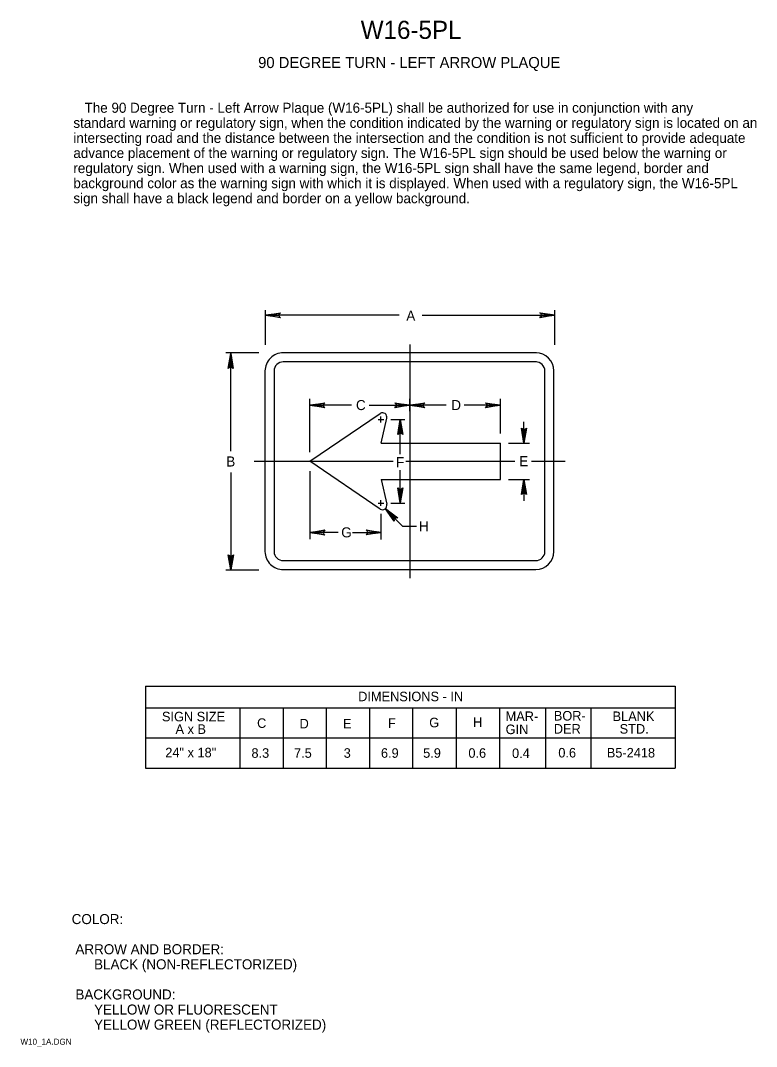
# Model space of a CAD drawing. Extents: x 0.013 to 0.196, y 0.004 to 0.259.
import ezdxf

# ---------------------------------------------------------------- set-up
doc = ezdxf.new("R2010")
doc.units = 0
for name, color, linetype in [('1', 7, 'Continuous'), ('2', 7, 'Continuous'), ('3', 7, 'Continuous')]:
    doc.layers.add(name, color=color, linetype=linetype)

# ---------------------------------------------------------------- blocks, each defined once
blk = doc.blocks.new('RARROW')
at = {"layer": '3'}
for p, q in [((-2.156, 0.28500000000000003), (-2.2665, 0.384625)), ((-2.2665, 0.384625), (0, 0)), ((0, 0), (-2.2665, -0.379125)), ((-2.156, 0.28500000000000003), (-2.075625, 0.12075)), ((0, 0), (-2.156, 0.28500000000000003)), ((-2.14975, -0.2705), (0, 0)), ((-2.075625, 0.12075), (0, 0)), ((0, 0), (-2.074, -0.108)), ((-2.2665, -0.379125), (-2.14975, -0.2705)), ((-2.074, -0.108), (-2.14975, -0.2705))]:
    blk.add_line(p, q, dxfattribs=at)

msp = doc.modelspace()

# ---------------------------------------------------------------- linework, layer by layer
at = {"layer": '1'}
for p, q in [((0.10950949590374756, 0.1784793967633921), (0.10950949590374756, 0.1204219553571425)), ((0.10234676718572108, 0.15397023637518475), (0.1320844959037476, 0.15397023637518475)), ((0.07079216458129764, 0.14947023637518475), (0.10538538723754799, 0.14947023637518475)), ((0.10848253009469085, 0.14947023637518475), (0.13531668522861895, 0.14947023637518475)), ((0.13531668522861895, 0.14947023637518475), (0.13561545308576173, 0.14947023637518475)), ((0.1398231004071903, 0.14947023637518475), (0.14818860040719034, 0.14947023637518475)), ((0.10234676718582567, 0.14497023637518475), (0.13208449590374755, 0.14497023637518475))]:
    msp.add_line(p, q, dxfattribs=at)
at = {"layer": '3'}
for p, q in [((0.07359843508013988, 0.17841642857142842), (0.07359843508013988, 0.18703855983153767)), ((0.1455984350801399, 0.17841642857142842), (0.1455984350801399, 0.18703855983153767)), ((0.10689328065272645, 0.18578855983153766), (0.07363359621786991, 0.18578855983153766)), ((0.1125947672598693, 0.18578855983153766), (0.1455984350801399, 0.18578855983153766)), ((0.07196701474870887, 0.17641355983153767), (0.0637585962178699, 0.17641355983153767)), ((0.0650085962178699, 0.1519761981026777), (0.0650085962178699, 0.17641355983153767)), ((0.14105197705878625, 0.17641642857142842), (0.07796701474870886, 0.17641642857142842)), ((0.14099731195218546, 0.17416642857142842), (0.07796701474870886, 0.17416642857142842)), ((0.07346701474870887, 0.17191642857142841), (0.07346701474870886, 0.12701630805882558)), ((0.07571701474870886, 0.17191642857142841), (0.07571701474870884, 0.1270163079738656)), ((0.14311543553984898, 0.12702017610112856), (0.14311543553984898, 0.171920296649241)), ((0.14536543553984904, 0.12702017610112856), (0.145365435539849, 0.171920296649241)), ((0.0846506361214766, 0.15176078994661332), (0.0846506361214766, 0.16495536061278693)), ((0.09499236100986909, 0.16340406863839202), (0.0846506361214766, 0.16340406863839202)), ((0.09939918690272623, 0.16340406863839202), (0.10950949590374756, 0.16340406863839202)), ((0.10950749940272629, 0.1619188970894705), (0.10950749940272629, 0.16495536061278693)), ((0.11854522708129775, 0.16340406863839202), (0.10950949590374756, 0.16340406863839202)), ((0.1320844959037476, 0.16340406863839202), (0.1230516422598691, 0.16340406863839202)), ((0.1320844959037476, 0.15633322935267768), (0.1320844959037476, 0.16495536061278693)), ((0.0846506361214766, 0.14947023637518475), (0.1021648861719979, 0.16137481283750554)), ((0.10161684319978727, 0.1598577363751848), (0.10233395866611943, 0.1598577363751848)), ((0.10233395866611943, 0.1598577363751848), (0.10233395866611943, 0.16057485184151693)), ((0.10233395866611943, 0.15914062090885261), (0.10233395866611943, 0.1598577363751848)), ((0.10233395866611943, 0.1598577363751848), (0.1030510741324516, 0.1598577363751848)), ((0.10234676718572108, 0.15397023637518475), (0.10377893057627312, 0.16017724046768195)), ((0.10481032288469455, 0.1598577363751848), (0.10825237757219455, 0.1598577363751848)), ((0.10712677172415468, 0.15126902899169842), (0.10712677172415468, 0.15904849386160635)), ((0.1379153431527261, 0.1539742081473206), (0.1379153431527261, 0.15928200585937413)), ((0.13208449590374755, 0.14497023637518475), (0.1320844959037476, 0.15397023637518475)), ((0.13410605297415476, 0.15397023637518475), (0.13925979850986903, 0.15397023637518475)), ((0.10216792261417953, 0.13755506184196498), (0.0846506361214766, 0.14947023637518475)), ((0.0650085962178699, 0.14667306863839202), (0.0650085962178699, 0.12258255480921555)), ((0.0846506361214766, 0.14704617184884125), (0.0846506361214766, 0.1301261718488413)), ((0.10712677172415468, 0.13909420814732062), (0.10712677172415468, 0.14722331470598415)), ((0.10234676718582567, 0.14497023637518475), (0.103778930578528, 0.13876323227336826)), ((0.13410605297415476, 0.14497023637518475), (0.13925979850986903, 0.14497023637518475)), ((0.1379153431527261, 0.14497023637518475), (0.1379153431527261, 0.13966243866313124)), ((0.10161684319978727, 0.13908273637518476), (0.10233395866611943, 0.13908273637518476)), ((0.10233395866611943, 0.13908273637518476), (0.10233395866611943, 0.13979985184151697)), ((0.10233395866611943, 0.13836562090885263), (0.10233395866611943, 0.13908273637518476)), ((0.10233395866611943, 0.13908273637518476), (0.1030510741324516, 0.13908273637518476)), ((0.10480954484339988, 0.13908273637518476), (0.10825159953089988, 0.13908273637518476)), ((0.10233395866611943, 0.1363890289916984), (0.10233395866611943, 0.12998902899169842)), ((0.1034524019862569, 0.13766902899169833), (0.10771129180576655, 0.13333585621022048)), ((0.10771129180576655, 0.13333585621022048), (0.11115334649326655, 0.13333585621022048)), ((0.09166954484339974, 0.13175474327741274), (0.0846506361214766, 0.13175474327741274)), ((0.09522383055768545, 0.13175474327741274), (0.10236383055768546, 0.13175474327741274)), ((0.07796701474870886, 0.12476630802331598), (0.14086543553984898, 0.12476630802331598)), ((0.07796701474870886, 0.12251630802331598), (0.14086543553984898, 0.12251630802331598)), ((0.07196701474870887, 0.12241355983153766), (0.0637585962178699, 0.12241355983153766)), ((0.043705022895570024, 0.09354213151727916), (0.17553288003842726, 0.09354213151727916)), ((0.043705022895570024, 0.09354213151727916), (0.043705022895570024, 0.07316713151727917)), ((0.17553288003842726, 0.09354213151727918), (0.17553288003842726, 0.07316713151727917)), ((0.043705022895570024, 0.08816713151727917), (0.17553288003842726, 0.08816713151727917)), ((0.06720502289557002, 0.08816713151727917), (0.06720502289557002, 0.07316713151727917)), ((0.07795502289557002, 0.08816713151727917), (0.07795502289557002, 0.07316713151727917)), ((0.08870502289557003, 0.08816713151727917), (0.08870502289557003, 0.07316713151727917)), ((0.09945502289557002, 0.08816713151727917), (0.09945502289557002, 0.07316713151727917)), ((0.11020502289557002, 0.08816713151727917), (0.11020502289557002, 0.07316713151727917)), ((0.12108002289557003, 0.08816713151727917), (0.12108002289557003, 0.07316713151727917)), ((0.13183002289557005, 0.08816713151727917), (0.13183002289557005, 0.07316713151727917)), ((0.14326428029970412, 0.08816713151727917), (0.14326428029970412, 0.07316713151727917)), ((0.1545968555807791, 0.08816713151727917), (0.1545968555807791, 0.07316713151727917)), ((0.043705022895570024, 0.08066713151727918), (0.17553288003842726, 0.08066713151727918)), ((0.043705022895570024, 0.07316713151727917), (0.17553288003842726, 0.07316713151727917))]:
    msp.add_line(p, q, dxfattribs=at)
for centre, radius, start, end in [((0.07799927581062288, 0.17188803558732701), 0.004532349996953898, 89.64106666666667, 179.6410666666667), ((0.14086543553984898, 0.171920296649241), 0.0045000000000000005, 0, 90), ((0.07799927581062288, 0.17188803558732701), 0.0022824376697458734, 89.28723611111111, 179.2872361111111), ((0.14086543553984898, 0.171920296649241), 0.0022500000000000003, 0, 90), ((0.102718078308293, 0.160433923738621), 0.0010914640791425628, 346.39815823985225, 120.45323601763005), ((0.102718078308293, 0.13850654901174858), 0.0010914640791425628, 239.54676398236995, 13.60184176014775), ((0.07799540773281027, 0.12704856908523), 0.004528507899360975, 180.4081777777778, 270.40817777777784), ((0.07799540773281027, 0.12704856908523), 0.002278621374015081, 180.81123055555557, 270.81123055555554), ((0.14086543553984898, 0.12702017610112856), 0.0045000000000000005, 270, 0), ((0.14086543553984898, 0.12702017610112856), 0.0022500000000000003, 270, 0)]:
    msp.add_arc(centre, radius, start, end, dxfattribs=at)

# ---------------------------------------------------------------- block references
for p, xscale, yscale, rotation in [((0.07359201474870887, 0.1857914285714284), 0.0016545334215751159, 0.0016366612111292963, 180), ((0.06496701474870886, 0.1762914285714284), 0.0016545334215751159, 0.0016366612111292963, 90), ((0.0846506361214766, 0.16340406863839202), 0.0016545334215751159, 0.0016366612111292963, 180), ((0.10950949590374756, 0.16340406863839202), 0.0016545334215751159, 0.0016366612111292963, 180), ((0.1071409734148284, 0.15988617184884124), 0.0016545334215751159, 0.0016366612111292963, 89.99999999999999), ((0.1379153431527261, 0.1539742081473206), 0.0016545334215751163, 0.0016366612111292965, -90.00000000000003), ((0.1379153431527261, 0.14497023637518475), 0.0016545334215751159, 0.0016366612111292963, 89.99999999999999), ((0.10712677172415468, 0.13909420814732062), 0.0016545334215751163, 0.0016366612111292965, -90.00000000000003), ((0.1034524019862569, 0.13766902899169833), 0.0016545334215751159, 0.0016366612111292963, 134.5046597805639), ((0.0846506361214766, 0.13175474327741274), 0.0016545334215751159, 0.0016366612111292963, 180), ((0.06496701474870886, 0.1224604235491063), 0.0016545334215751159, 0.0016366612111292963, -90)]:
    msp.add_blockref('RARROW', p, dxfattribs=dict(at, xscale=xscale, yscale=yscale, rotation=rotation))
at = {"layer": '3', "xscale": 0.0016545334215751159, "yscale": 0.0016366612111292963}
for p in [(0.1455984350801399, 0.18578855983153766), (0.10950949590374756, 0.16340406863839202), (0.1320844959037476, 0.16340406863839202), (0.10236383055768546, 0.13175474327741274)]:
    msp.add_blockref('RARROW', p, dxfattribs=at)

# ---------------------------------------------------------------- texts
at = {"layer": '1'}
for s, height, p in [('W16-5PL', 0.0045000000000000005, (0.0972959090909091, 0.2545)), ('90 DEGREE TURN - LEFT ARROW PLAQUE', 0.00275025, (0.07176388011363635, 0.24725)), ('COLOR:', 0.0024997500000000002, (0.025375, 0.034374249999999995)), (' ARROW AND BORDER:', 0.0024997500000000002, (0.025375, 0.02687475)), ('      BLACK (NON-REFLECTORIZED)', 0.0024997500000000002, (0.025375, 0.023125)), (' BACKGROUND:', 0.0024997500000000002, (0.025375, 0.0156255)), ('      YELLOW OR FLUORESCENT ', 0.0024997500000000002, (0.025375, 0.011875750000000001)), ('      YELLOW GREEN (REFLECTORIZED)', 0.0024997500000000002, (0.025375, 0.008126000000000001)), ('W10_1A.DGN', 0.0015, (0.012625, 0.004375))]:
    msp.add_text(s, height=height, dxfattribs=at).set_placement(p)
at = {"layer": '2'}
for s, p in [('   The 90 Degree Turn - Left Arrow Plaque (W16-5PL) shall be authorized for use in conjunction with any ', (0.02578829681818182, 0.23612525)), ('standard warning or regulatory sign, when the condition indicated by the warning or regulatory sign is located on an', (0.02578829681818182, 0.23237549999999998)), ('intersecting road and the distance between the intersection and the condition is not sufficient to provide adequate ', (0.02578829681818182, 0.22862575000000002)), ('advance placement of the warning or regulatory sign. The W16-5PL sign should be used below the warning or ', (0.02578829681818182, 0.22487600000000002)), ('regulatory sign. When used with a warning sign, the W16-5PL sign shall have the same legend, border and ', (0.02578829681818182, 0.22112625)), ('background color as the warning sign with which it is displayed. When used with a regulatory sign, the W16-5PL ', (0.02578829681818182, 0.2173765)), ('sign shall have a black legend and border on a yellow background.', (0.02578829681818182, 0.21362675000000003))]:
    msp.add_text(s, height=0.0024997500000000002, dxfattribs=at).set_placement(p)
at = {"layer": '3'}
for s, height, p in [('A', 0.0024997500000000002, (0.10864247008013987, 0.18441642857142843)), ('C', 0.0024997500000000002, (0.09612310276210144, 0.1621903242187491)), ('D', 0.0024997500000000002, (0.11984103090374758, 0.1621903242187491)), ('B', 0.0024997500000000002, (0.06384201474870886, 0.14816368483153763)), ('E', 0.0024997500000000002, (0.13677120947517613, 0.14824782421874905)), ('F', 0.0024997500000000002, (0.10608103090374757, 0.14798902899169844)), ('G', 0.0024997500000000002, (0.09244310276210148, 0.13054099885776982)), ('H', 0.0024997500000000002, (0.11179531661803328, 0.13206902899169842)), ('DIMENSIONS - IN', 0.0023752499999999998, (0.09666124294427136, 0.08979213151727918)), ('SIGN SIZE', 0.0023752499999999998, (0.04783002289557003, 0.08479213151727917)), ('MAR-', 0.0023752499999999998, (0.13334707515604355, 0.08486676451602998)), ('BOR-', 0.0023752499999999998, (0.14534707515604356, 0.08499176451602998)), ('BLANK', 0.0023752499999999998, (0.1599720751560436, 0.08486676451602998)), ('C', 0.0023752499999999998, (0.07150814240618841, 0.08316713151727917)), ('D', 0.0023752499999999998, (0.08208002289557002, 0.08304213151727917)), ('E', 0.0023752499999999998, (0.09290002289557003, 0.08304213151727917)), ('F', 0.0023752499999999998, (0.10408002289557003, 0.08316713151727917)), ('G', 0.0023752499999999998, (0.11434288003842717, 0.08330564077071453)), ('H', 0.0023752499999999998, (0.1252581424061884, 0.08339561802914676)), ('A x B', 0.0023752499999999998, (0.051205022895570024, 0.08166713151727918)), ('GIN', 0.0023752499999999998, (0.13334707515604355, 0.08161676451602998)), ('DER', 0.0023752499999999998, (0.14534707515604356, 0.08174176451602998)), ('STD.', 0.0023752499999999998, (0.16172207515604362, 0.08174176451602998)), ('24" x 18"', 0.0023752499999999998, (0.04866636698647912, 0.07585450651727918)), ('8.3', 0.0023752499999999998, (0.07010808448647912, 0.07572950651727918)), ('7.5', 0.0023752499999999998, (0.0807014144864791, 0.07572950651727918)), ('3', 0.0023752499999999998, (0.0930587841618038, 0.07572950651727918)), ('6.9', 0.0023752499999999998, (0.10232713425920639, 0.07572950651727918)), ('5.9', 0.0023752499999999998, (0.11282713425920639, 0.07572950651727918)), ('0.6', 0.0023752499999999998, (0.12408710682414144, 0.07572950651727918)), ('0.4', 0.0023752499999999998, (0.13495407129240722, 0.07567913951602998)), ('0.6', 0.0023752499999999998, (0.14646558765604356, 0.07580413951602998)), ('B5-2418', 0.0023752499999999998, (0.15853243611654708, 0.07580413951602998))]:
    msp.add_text(s, height=height, dxfattribs=at).set_placement(p)

doc.saveas('drawing.dxf')
